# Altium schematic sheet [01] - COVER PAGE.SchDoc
size A3; DocumentNumber: 1; SheetNumber: 1; SheetTotal: 5
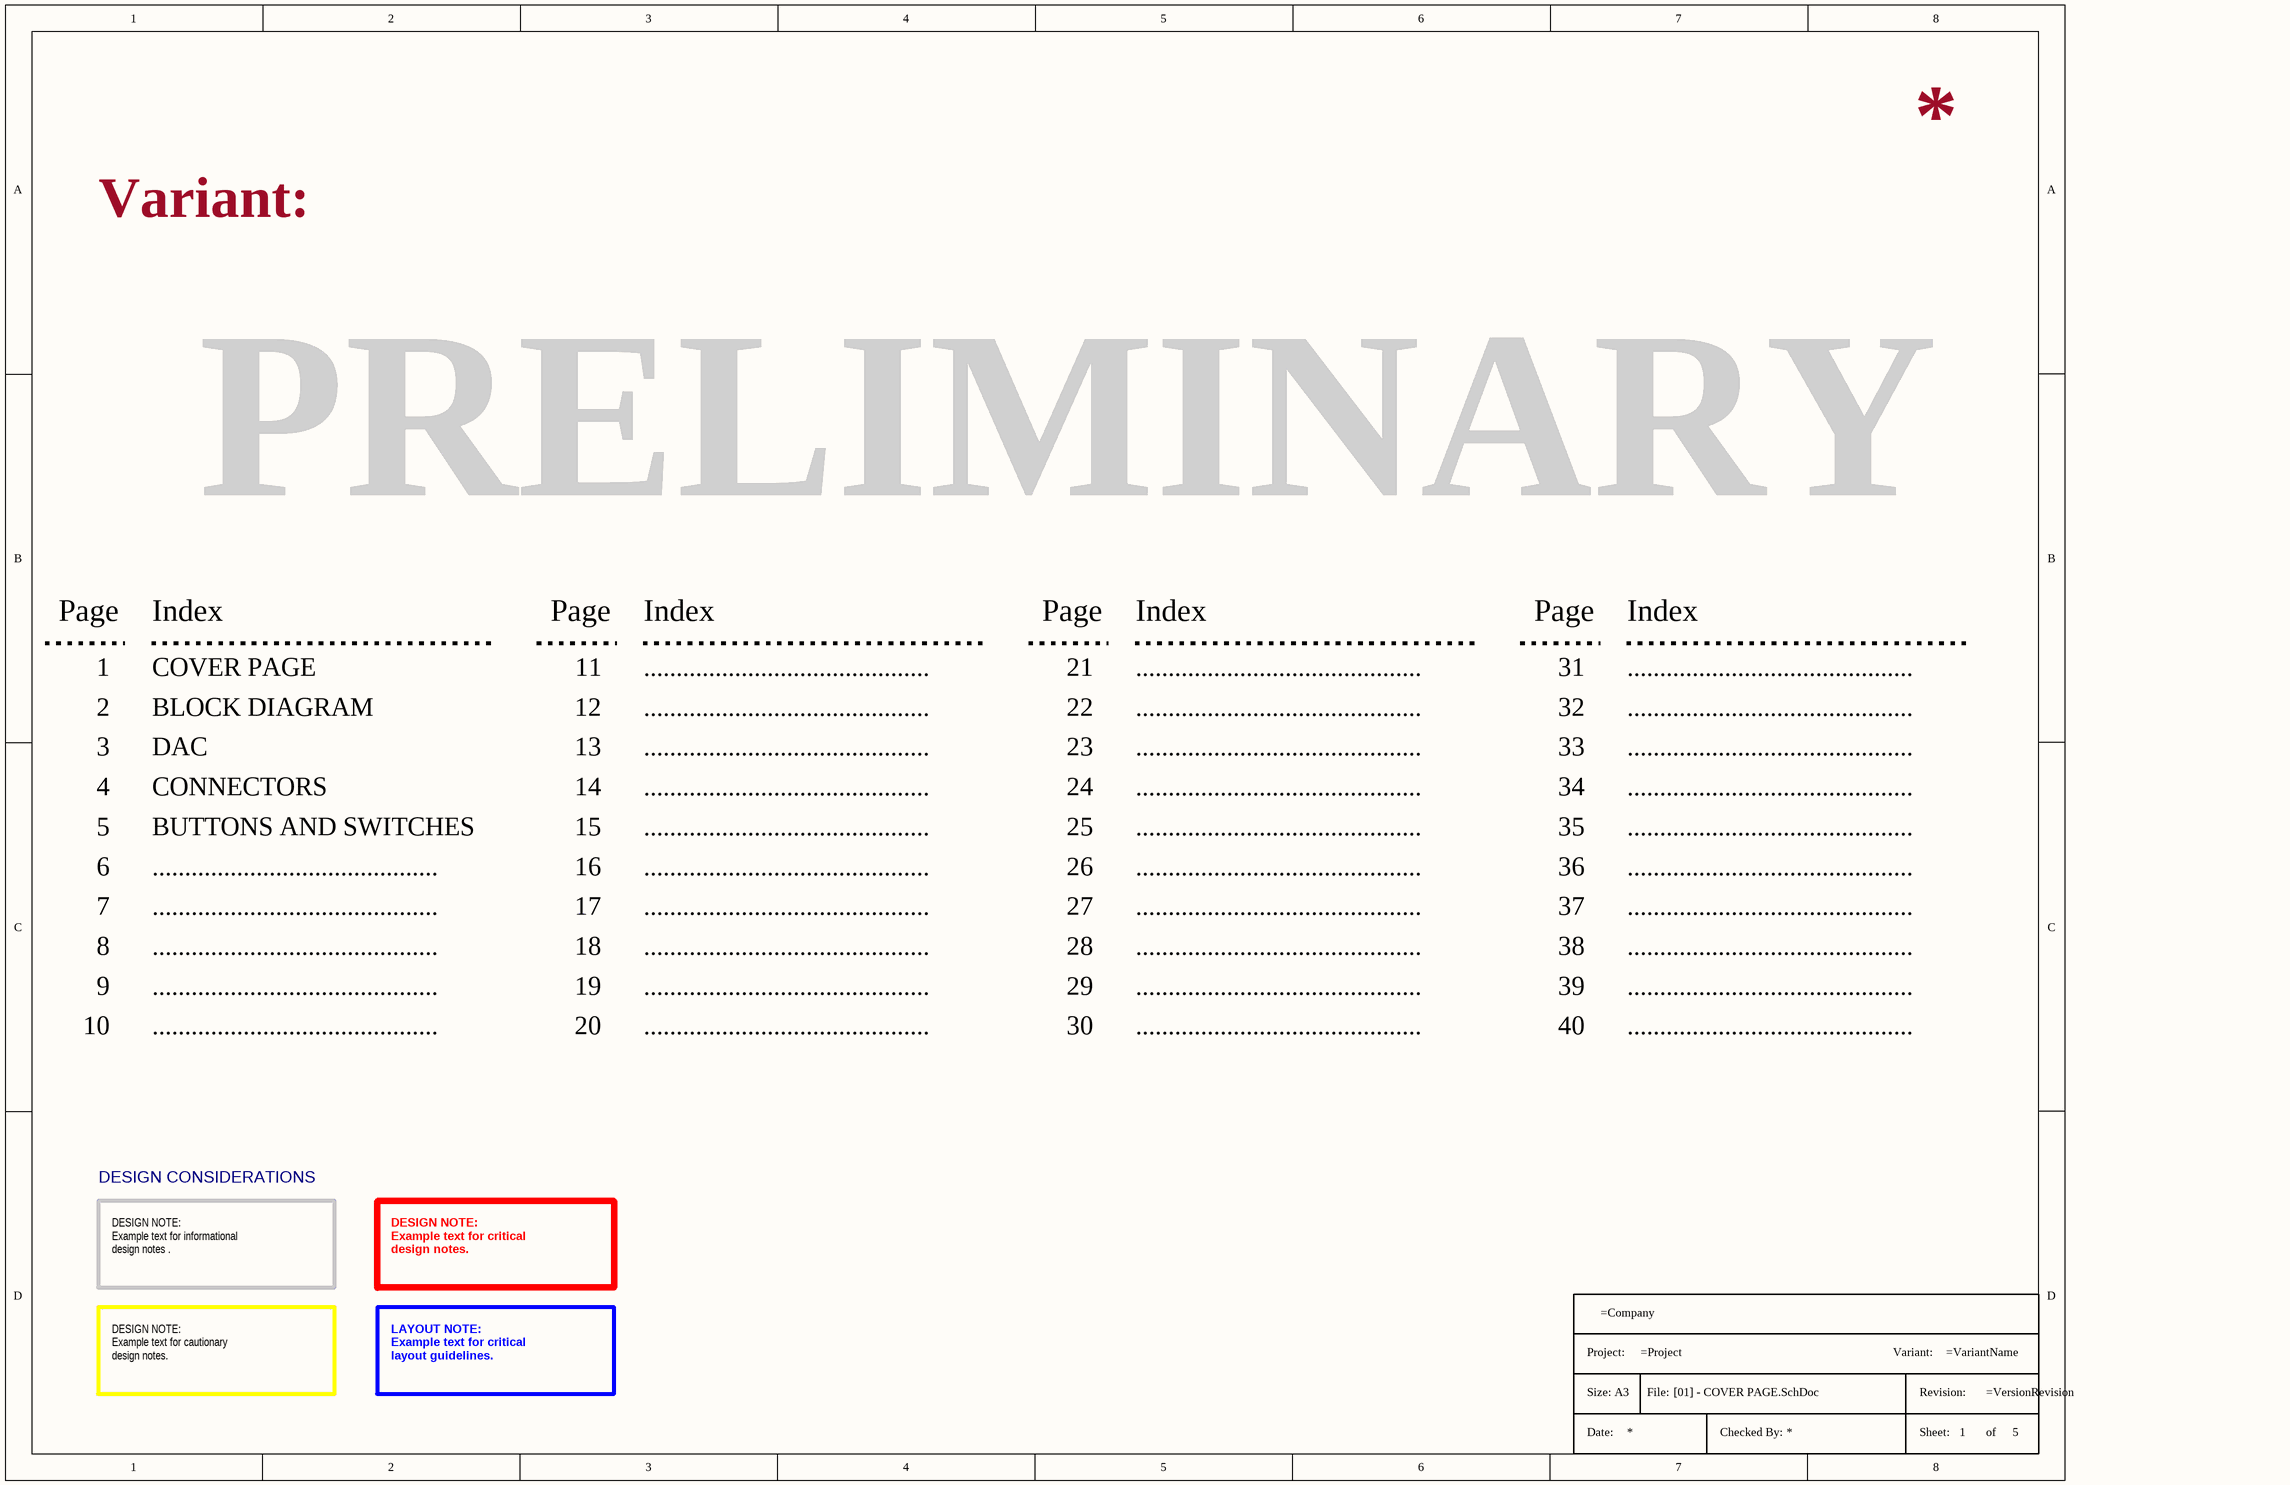
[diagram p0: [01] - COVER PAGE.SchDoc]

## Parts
*  Title Block A3  (value not drawn)  (graphical)

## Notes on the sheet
- Variant:
- PRELIMINARY
- Page
- Index
- 1
- COVER PAGE
- 11
- ............................................
- 21
- 31
- 2
- 3
- BLOCK DIAGRAM
- DAC
- 12
- 13
- 22
- 23
- 32
- 33
- 4
- 5
- CONNECTORS
- BUTTONS AND SWITCHES
- 14
- 15
- 24
- 25
- 34
- 35
- 6
- 16
- 26
- 36
- 7
- 8
- 17
- 18
- 27
- 28
- 37
- 38
- 9
- 10
- 19
- 20
- 29
- 30
- 39
- 40
- DESIGN CONSIDERATIONS
- DESIGN NOTE:
  Example text for informational
  design notes .
- DESIGN NOTE:
  Example text for critical
  design notes.
- DESIGN NOTE:
  Example text for cautionary
  design notes.
- LAYOUT NOTE:
  Example text for critical
  layout guidelines.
